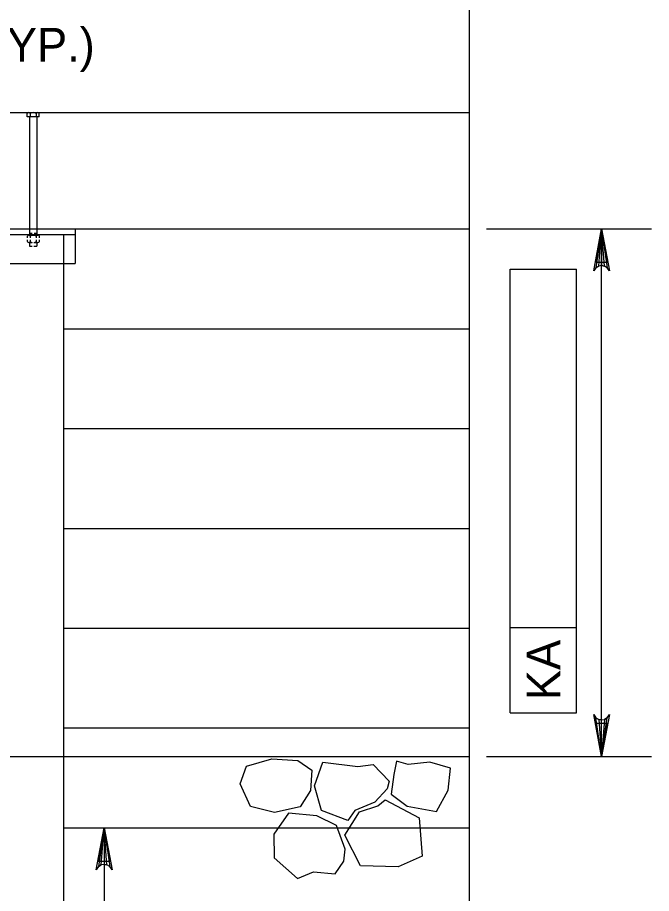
# Model space of a CAD drawing. Extents: x 635440 to 640306, y 296653 to 298484.
# Drawn here: x 639579.4 to 639635.7, y 297963.1 to 298040.8 of the extents above; entities that cross this region are included whole.
import ezdxf

# ---------------------------------------------------------------- set-up
doc = ezdxf.new("R2010")
doc.units = 0
for name, color, linetype in [('3', 7, 'Continuous'), ('4', 7, 'Continuous'), ('8', 7, 'Continuous')]:
    doc.layers.add(name, color=color, linetype=linetype)

# ---------------------------------------------------------------- blocks, each defined once
blk = doc.blocks.new('ROCK')
at = {"layer": '4'}
for points in [[(2.36725, 1.088), (2.2065, 0.82625), (2.378625, 0.506625), (2.66975, 0.3095), (3.128875, 0.403375), (3.48475, 0.6775), (3.4915, 1.123375), (3.25625, 1.36725), (2.783625, 1.308375)], [(1.10175, -0.02725), (1.4015, -0.159125), (1.78825, -0.148875), (1.980875, -0.266), (2.343375, 0.09475), (2.27875, 0.5505), (1.969375, 0.883), (1.4225, 0.553625), (1.152875, 0.479), (1.0105, 0.082)], [(0.74675, 0.359875), (0.882, 0.16), (1.072875, -0.144), (0.892, -0.457375), (0.448125, -0.758625), (0.1, -0.49325), (-0.095, -0.146375), (0.202875, 0.1025), (0.579125, 0.219875)], [(2.231375, -0.71725), (2.2025, -0.266375), (2.45475, 0.037125), (2.9085, 0.28875), (3.2995, 0.047625), (3.46875, -0.344), (3.231625, -0.855), (2.92, -0.860375), (2.5765, -1.054625), (2.340375, -0.904375)], [(1.2085, -0.192875), (0.778375, -0.737625), (1.008375, -1.391375), (1.48725, -1.396875), (2.09825, -1.106625), (2.133375, -0.486375), (1.723125, -0.203375), (1.37425, -0.239875)]]:
    blk.add_lwpolyline(points, close=True, dxfattribs=at)

msp = doc.modelspace()

# ---------------------------------------------------------------- linework, layer by layer
at = {"layer": '3'}
for p, q in [((639462.829, 298032.371), (639619.557, 298032.371)), ((639580.299, 298031.973), (639580.299, 298032.277)), ((639580.422, 298032.371), (639581.231, 298032.371)), ((639580.46, 298032.366), (639580.46, 298032.366)), ((639580.474, 298032.366), (639580.474, 298032.366)), ((639580.489, 298032.366), (639580.489, 298032.366)), ((639580.495, 298032.352), (639580.495, 298032.352)), ((639580.504, 298032.366), (639580.504, 298032.366)), ((639580.512, 298032.352), (639580.512, 298032.352)), ((639580.518, 298032.366), (639580.518, 298032.366)), ((639580.518, 298032.337), (639580.518, 298032.337)), ((639580.526, 298032.352), (639580.526, 298032.352)), ((639580.533, 298032.366), (639580.533, 298032.366)), ((639580.533, 298032.337), (639580.533, 298032.337)), ((639580.541, 298032.352), (639580.541, 298032.352)), ((639580.541, 298032.323), (639580.541, 298032.323)), ((639580.547, 298032.366), (639580.547, 298032.366)), ((639580.547, 298032.337), (639580.547, 298032.337)), ((639580.547, 298032.308), (639580.547, 298032.308)), ((639580.556, 298032.352), (639580.556, 298032.352)), ((639580.556, 298032.323), (639580.556, 298032.323)), ((639580.556, 298032.294), (639580.556, 298032.294)), ((639580.556, 298032.277), (639580.556, 298031.973)), ((639580.558, 298032.352), (639580.558, 298032.352)), ((639580.558, 298032.323), (639580.558, 298032.323)), ((639580.558, 298032.294), (639580.558, 298032.294)), ((639580.564, 298032.366), (639580.564, 298032.366)), ((639580.564, 298032.337), (639580.564, 298032.337)), ((639580.564, 298032.308), (639580.564, 298032.308)), ((639580.572, 298032.352), (639580.572, 298032.352)), ((639580.572, 298032.323), (639580.572, 298032.323)), ((639580.572, 298032.294), (639580.572, 298032.294)), ((639580.581, 298032.366), (639580.581, 298032.366)), ((639580.581, 298032.337), (639580.581, 298032.337)), ((639580.581, 298032.308), (639580.581, 298032.308)), ((639580.587, 298032.352), (639580.587, 298032.352)), ((639580.587, 298032.323), (639580.587, 298032.323)), ((639580.595, 298032.366), (639580.595, 298032.366)), ((639580.595, 298032.337), (639580.595, 298032.337)), ((639580.595, 298032.308), (639580.595, 298032.308)), ((639580.601, 298032.352), (639580.601, 298032.352)), ((639580.601, 298032.323), (639580.601, 298032.323)), ((639580.61, 298032.366), (639580.61, 298032.366)), ((639580.61, 298032.337), (639580.61, 298032.337)), ((639580.616, 298032.352), (639580.616, 298032.352)), ((639580.616, 298032.323), (639580.616, 298032.323)), ((639580.624, 298032.366), (639580.624, 298032.366)), ((639580.624, 298032.337), (639580.624, 298032.337)), ((639580.633, 298032.352), (639580.633, 298032.352)), ((639580.639, 298032.366), (639580.639, 298032.366)), ((639580.639, 298032.337), (639580.639, 298032.337)), ((639580.645, 298032.352), (639580.645, 298032.352)), ((639580.654, 298032.366), (639580.654, 298032.366)), ((639580.654, 298032.337), (639580.654, 298032.337)), ((639580.662, 298032.352), (639580.662, 298032.352)), ((639580.668, 298032.366), (639580.668, 298032.366)), ((639580.676, 298032.352), (639580.676, 298032.352)), ((639580.683, 298032.366), (639580.683, 298032.366)), ((639580.691, 298032.352), (639580.691, 298032.352)), ((639580.697, 298032.366), (639580.697, 298032.366)), ((639580.714, 298032.366), (639580.714, 298032.366)), ((639580.726, 298032.366), (639580.726, 298032.366)), ((639580.743, 298032.366), (639580.743, 298032.366)), ((639580.758, 298032.366), (639580.758, 298032.366)), ((639580.891, 298032.366), (639580.891, 298032.366)), ((639580.904, 298032.366), (639580.904, 298032.366)), ((639580.92, 298032.366), (639580.92, 298032.366)), ((639580.935, 298032.366), (639580.935, 298032.366)), ((639580.949, 298032.366), (639580.949, 298032.366)), ((639580.956, 298032.352), (639580.956, 298032.352)), ((639580.964, 298032.366), (639580.964, 298032.366)), ((639580.972, 298032.352), (639580.972, 298032.352)), ((639580.979, 298032.366), (639580.979, 298032.366)), ((639580.987, 298032.352), (639580.987, 298032.352)), ((639580.993, 298032.366), (639580.993, 298032.366)), ((639580.993, 298032.337), (639580.993, 298032.337)), ((639580.999, 298032.352), (639580.999, 298032.352)), ((639581.008, 298032.366), (639581.008, 298032.366)), ((639581.008, 298032.337), (639581.008, 298032.337)), ((639581.016, 298032.352), (639581.016, 298032.352)), ((639581.022, 298032.366), (639581.022, 298032.366)), ((639581.022, 298032.337), (639581.022, 298032.337)), ((639581.031, 298032.352), (639581.031, 298032.352)), ((639581.031, 298032.323), (639581.031, 298032.323)), ((639581.037, 298032.366), (639581.037, 298032.366)), ((639581.037, 298032.337), (639581.037, 298032.337)), ((639581.045, 298032.352), (639581.045, 298032.352)), ((639581.045, 298032.323), (639581.045, 298032.323)), ((639581.051, 298032.366), (639581.051, 298032.366)), ((639581.051, 298032.337), (639581.051, 298032.337)), ((639581.051, 298032.308), (639581.051, 298032.308)), ((639581.06, 298032.352), (639581.06, 298032.352)), ((639581.06, 298032.323), (639581.06, 298032.323)), ((639581.068, 298032.366), (639581.068, 298032.366)), ((639581.068, 298032.337), (639581.068, 298032.337)), ((639581.068, 298032.308), (639581.068, 298032.308)), ((639581.074, 298032.352), (639581.074, 298032.352)), ((639581.074, 298032.323), (639581.074, 298032.323)), ((639581.074, 298032.294), (639581.074, 298032.294)), ((639581.081, 298032.366), (639581.081, 298032.366)), ((639581.081, 298032.337), (639581.081, 298032.337)), ((639581.081, 298032.308), (639581.081, 298032.308)), ((639581.089, 298032.352), (639581.089, 298032.352)), ((639581.089, 298032.323), (639581.089, 298032.323)), ((639581.089, 298032.294), (639581.089, 298032.294)), ((639581.089, 298032.277), (639581.089, 298031.973)), ((639581.097, 298032.366), (639581.097, 298032.366)), ((639581.097, 298032.337), (639581.097, 298032.337)), ((639581.097, 298032.308), (639581.097, 298032.308)), ((639581.104, 298032.352), (639581.104, 298032.352)), ((639581.104, 298032.323), (639581.104, 298032.323)), ((639581.112, 298032.366), (639581.112, 298032.366)), ((639581.112, 298032.337), (639581.112, 298032.337)), ((639581.118, 298032.352), (639581.118, 298032.352)), ((639581.126, 298032.366), (639581.126, 298032.366)), ((639581.126, 298032.337), (639581.126, 298032.337)), ((639581.133, 298032.352), (639581.133, 298032.352)), ((639581.141, 298032.366), (639581.141, 298032.366)), ((639581.149, 298032.352), (639581.149, 298032.352)), ((639581.156, 298032.366), (639581.156, 298032.366)), ((639581.17, 298032.366), (639581.17, 298032.366)), ((639581.185, 298032.366), (639581.185, 298032.366)), ((639581.364, 298031.973), (639581.364, 298032.277)), ((639581.364, 298031.973), (639580.299, 298031.973)), ((639580.504, 298031.973), (639580.504, 298021.476)), ((639581.16, 298031.973), (639581.16, 298021.476)), ((639462.829, 298022.035), (639619.557, 298022.035)), ((639580.308, 298021.235), (639580.308, 298021.383)), ((639580.433, 298021.476), (639581.241, 298021.476)), ((639580.504, 298021.658), (639580.741, 298021.658)), ((639580.566, 298021.383), (639580.566, 298021.235)), ((639580.921, 298021.658), (639581.16, 298021.658)), ((639581.099, 298021.383), (639581.099, 298021.235)), ((639581.374, 298021.235), (639581.374, 298021.383)), ((639584.55, 298022.035), (639584.55, 298018.96)), ((639580.308, 298020.924), (639580.308, 298021.083)), ((639580.433, 298020.831), (639580.741, 298020.831)), ((639580.504, 298020.831), (639580.504, 298020.51)), ((639580.566, 298021.083), (639580.566, 298020.924)), ((639580.891, 298020.831), (639581.241, 298020.831)), ((639581.099, 298021.083), (639581.099, 298020.924)), ((639581.16, 298020.831), (639581.16, 298020.51)), ((639581.374, 298020.924), (639581.374, 298021.083)), ((639580.504, 298020.51), (639580.741, 298020.51)), ((639580.891, 298020.51), (639581.16, 298020.51)), ((639572.17, 298018.96), (639584.55, 298018.96)), ((639583.525, 298018.96), (639583.525, 297975.214)), ((639583.525, 298013.176), (639619.557, 298013.176)), ((639583.525, 298004.317), (639619.557, 298004.317)), ((639583.525, 297995.459), (639619.557, 297995.459)), ((639583.525, 297986.6), (639619.557, 297986.6)), ((639583.525, 297977.741), (639619.557, 297977.741)), ((639469.948, 297975.214), (639619.557, 297975.214)), ((639583.525, 297975.214), (639583.525, 297930.62)), ((639583.525, 297968.882), (639619.557, 297968.882))]:
    msp.add_line(p, q, dxfattribs=at)
for centre, radius, start, end in [((639580.427, 298032.236), 0.135, 17.45181, 162.54819), ((639580.822, 298031.947), 0.424, 51.05, 128.95), ((639581.226, 298032.223), 0.148, 91.82706, 158.71306), ((639581.226, 298032.223), 0.148, 21.28694, 91.82706), ((639580.438, 298021.341), 0.135, 17.45181, 162.54819), ((639580.833, 298021.052), 0.424, 51.05, 128.95), ((639581.237, 298021.328), 0.148, 91.82706, 158.71306), ((639581.237, 298021.328), 0.148, 21.28694, 91.82706), ((639580.438, 298020.965), 0.135, 197.45181, 342.54819), ((639580.833, 298021.254), 0.424, 231.05, 257.49177), ((639580.833, 298021.254), 0.424, 277.88621, 308.95), ((639581.237, 298020.978), 0.148, 201.28694, 268.17294), ((639581.237, 298020.978), 0.148, 268.17294, 338.71305)]:
    msp.add_arc(centre, radius, start, end, dxfattribs=at)
at = {"layer": '4'}
for p, q in [((639619.557, 298050.659), (639619.557, 297940.454)), ((639621.095, 298022.035), (639635.737, 298022.035)), ((639631.308, 297975.214), (639631.308, 298022.035)), ((639623.185, 297979.089), (639623.185, 298018.462)), ((639623.185, 298018.462), (639629.089, 298018.462)), ((639629.089, 297979.089), (639629.089, 298018.462)), ((639623.185, 297986.652), (639629.089, 297986.652)), ((639623.185, 297979.089), (639629.089, 297979.089)), ((639621.095, 297975.214), (639635.737, 297975.214)), ((639587.123, 297968.882), (639587.123, 297942.527))]:
    msp.add_line(p, q, dxfattribs=at)
for points in [[(639631.308, 298022.035), (639632.008, 298018.305), (639631.808, 298018.593), (639631.558, 298018.741), (639631.308, 298018.785), (639631.058, 298018.741), (639630.808, 298018.593), (639630.608, 298018.305), (639631.308, 298022.035), (639630.808, 298018.593), (639631.058, 298018.741), (639631.308, 298022.035), (639631.308, 298018.785), (639631.558, 298018.741), (639631.308, 298022.035), (639631.808, 298018.593)], [(639631.308, 297975.214), (639630.608, 297978.943), (639630.808, 297978.656), (639631.058, 297978.508), (639631.308, 297978.464), (639631.558, 297978.508), (639631.808, 297978.656), (639632.008, 297978.943), (639631.308, 297975.214), (639631.808, 297978.656), (639631.558, 297978.508), (639631.308, 297975.214), (639631.308, 297978.464), (639631.058, 297978.508), (639631.308, 297975.214), (639630.808, 297978.656)], [(639587.123, 297968.882), (639587.823, 297965.153), (639587.623, 297965.44), (639587.373, 297965.588), (639587.123, 297965.632), (639586.873, 297965.588), (639586.623, 297965.44), (639586.423, 297965.153), (639587.123, 297968.882), (639586.623, 297965.44), (639586.873, 297965.588), (639587.123, 297968.882), (639587.123, 297965.632), (639587.373, 297965.588), (639587.123, 297968.882), (639587.623, 297965.44)]]:
    msp.add_lwpolyline(points, dxfattribs=at)
for points in [[(639630.814, 298019.083), (639631.8, 298019.083), (639631.308, 298022.035)], [(639630.814, 297978.168), (639631.8, 297978.168), (639631.308, 297975.214)], [(639586.631, 297965.93), (639587.614, 297965.93), (639587.123, 297968.882)]]:
    msp.add_lwpolyline(points, close=True, dxfattribs=at)
at = {"layer": '8'}
for p, q in [((639572.17, 298021.543), (639584.55, 298021.543)), ((639583.525, 298021.543), (639583.525, 298018.96))]:
    msp.add_line(p, q, dxfattribs=at)

# ---------------------------------------------------------------- block references
at = {"layer": '4', "xscale": 4.921475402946, "yscale": -4.921475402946, "rotation": -156.2166383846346}
msp.add_blockref('ROCK', (639617.157, 297974.645), dxfattribs=at)

# ---------------------------------------------------------------- texts
at = {"layer": '4'}
msp.add_text('NUT & WASHERS (TYP.)', height=3.00014, dxfattribs=at).set_placement((639540.152, 298036.881))
msp.add_text('KA', height=3.0001, rotation=90, dxfattribs=at).set_placement((639627.637, 297980.214))

doc.saveas('drawing.dxf')
